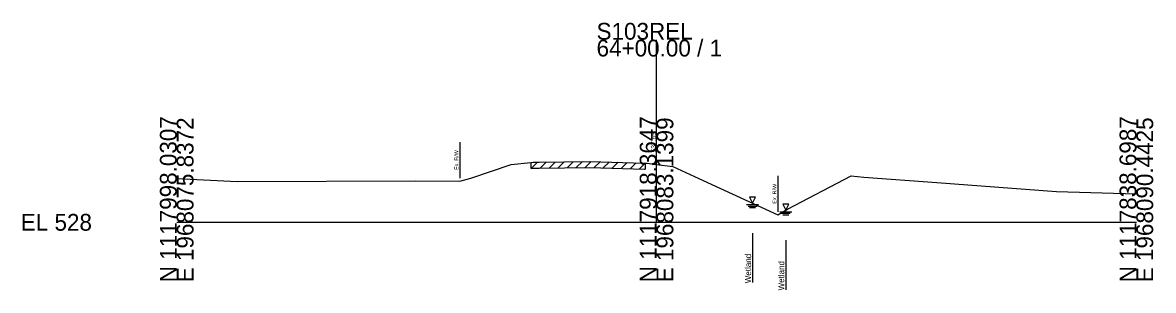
# Model space of a CAD drawing. Extents: x -26 to 163, y -10 to 24518.
# Drawn here: x -25.7 to 162.8, y 11988.6 to 12033.3 of the extents above; entities that cross this region are included whole.
import ezdxf

# ---------------------------------------------------------------- set-up
doc = ezdxf.new("R2010")
doc.units = 0
for name, color, linetype in [('RD_GPK_XS_Cell', 7, 'Continuous'), ('RD_XS_ExGround', 7, 'Continuous'), ('RD_XS_ExPaveRet', 7, 'Continuous'), ('RD_XS_ExRW', 7, 'Continuous'), ('RD_XS_EXWetland', 7, 'Continuous'), ('RD_XS_TX_Elev_EX', 7, 'Continuous')]:
    doc.layers.add(name, color=color, linetype=linetype)

msp = doc.modelspace()

# ---------------------------------------------------------------- linework, layer by layer
at = {"layer": 'RD_GPK_XS_Cell'}
for p, q in [((80, 12000), (80, 12030.44)), ((0, 12000), (80, 12000)), ((80, 12000), (160, 12000))]:
    msp.add_line(p, q, dxfattribs=at)
at = {"layer": 'RD_XS_ExGround'}
msp.add_lwpolyline([(0, 12007.32), (10.08, 12006.8), (39.8, 12006.92), (47.23, 12006.88), (49.04, 12007.38), (55.74, 12009.63), (59.04, 12009.96), (59.43, 12010), (60.41, 12010), (68.87, 12010.15), (77.99, 12009.86), (78.45, 12009.84), (80, 12009.65), (82.73, 12009.31), (87.78, 12006.98), (100.24, 12001.26), (101.85, 12002.18), (112.46, 12007.76), (114.57, 12007.52), (126.73, 12006.66), (146.71, 12005.13), (160, 12004.73)], dxfattribs=at)
at = {"layer": 'RD_XS_ExPaveRet'}
for p, q in [((59.09, 12008.96), (60.13, 12010)), ((59.09, 12008.96), (59.09, 12009.96)), ((60.59, 12009.01), (61.61, 12010.03)), ((62.1, 12009.03), (63.12, 12010.05)), ((63.6, 12009.06), (64.62, 12010.08)), ((65.1, 12009.08), (66.12, 12010.1)), ((66.61, 12009.11), (67.63, 12010.13)), ((68.11, 12009.14), (69.12, 12010.14)), ((69.61, 12009.12), (70.59, 12010.09)), ((71.12, 12009.08), (72.09, 12010.05)), ((72.62, 12009.03), (73.59, 12010)), ((74.12, 12008.98), (75.1, 12009.95)), ((75.63, 12008.93), (76.6, 12009.9)), ((77.13, 12008.88), (78.1, 12009.85)), ((78.13, 12009.85), (78.13, 12008.85)), ((59.09, 12008.96), (59.43, 12009)), ((59.43, 12009), (60.41, 12009)), ((60.41, 12009), (68.87, 12009.15)), ((68.87, 12009.15), (77.99, 12008.86)), ((77.99, 12008.86), (78.13, 12008.85))]:
    msp.add_line(p, q, dxfattribs=at)
at = {"layer": 'RD_XS_ExRW'}
for p, q in [((47.21, 12013.38), (47.21, 12007.38)), ((100.25, 12007.76), (100.25, 12001.76))]:
    msp.add_line(p, q, dxfattribs=at)
at = {"layer": 'RD_XS_EXWetland'}
for p, q in [((95.52, 12004.2), (96.02, 12003.2)), ((96.52, 12004.2), (95.52, 12004.2)), ((95.52, 12004.2), (96.02, 12003.2)), ((96.52, 12004.2), (95.52, 12004.2)), ((96.02, 12003.2), (96.52, 12004.2)), ((96.02, 12003.2), (96.52, 12004.2)), ((95.02, 12002.95), (97.02, 12002.95)), ((95.02, 12002.95), (97.02, 12002.95)), ((95.27, 12002.7), (96.77, 12002.7)), ((95.27, 12002.7), (96.77, 12002.7)), ((95.52, 12002.45), (96.52, 12002.45)), ((95.52, 12002.45), (96.52, 12002.45)), ((101.04, 12003), (101.54, 12002)), ((102.04, 12003), (101.04, 12003)), ((101.04, 12003), (101.54, 12002)), ((102.04, 12003), (101.04, 12003)), ((101.54, 12002), (102.04, 12003)), ((101.54, 12002), (102.04, 12003)), ((100.54, 12001.75), (102.54, 12001.75)), ((100.54, 12001.75), (102.54, 12001.75)), ((100.79, 12001.5), (102.29, 12001.5)), ((100.79, 12001.5), (102.29, 12001.5)), ((101.04, 12001.25), (102.04, 12001.25)), ((101.04, 12001.25), (102.04, 12001.25)), ((96.02, 11998.2), (96.02, 11989.95)), ((96.02, 11998.2), (96.02, 11989.95)), ((101.54, 11997), (101.54, 11988.75)), ((101.54, 11997), (101.54, 11988.75))]:
    msp.add_line(p, q, dxfattribs=at)

# ---------------------------------------------------------------- texts
at = {"layer": 'RD_GPK_XS_Cell'}
for s, p in [('S103REL', (70, 12030.44)), ('64+00.00 / 1', (70, 12027.64)), ('EL 528', (-26, 11998.6))]:
    msp.add_text(s, height=2.8, dxfattribs=at).set_placement(p)
for s, p in [('N 1117998.0307', (0, 11990)), ('E 1968075.8372', (2.8, 11990)), ('N 1117918.3647', (80, 11990)), ('E 1968083.1399', (82.8, 11990)), ('N 1117838.6987', (160, 11990)), ('E 1968090.4425', (162.8, 11990))]:
    msp.add_text(s, height=2.8, rotation=90, dxfattribs=at).set_placement(p)
at = {"layer": 'RD_XS_ExRW'}
for p in [(46.96, 12008.73), (100, 12003.11)]:
    msp.add_text('Ex. R/W ', height=0.65, rotation=90, dxfattribs=at).set_placement(p)
at = {"layer": 'RD_XS_EXWetland'}
for p in [(95.77, 11989.84), (95.77, 11989.84), (101.29, 11988.64), (101.29, 11988.64)]:
    msp.add_text('Wetland ', height=1, rotation=90, dxfattribs=at).set_placement(p)
at = {"layer": 'RD_XS_TX_Elev_EX'}
msp.add_text('537.65', height=0.8, rotation=90, dxfattribs=at).set_placement((79.9, 12011.65))

doc.saveas('drawing.dxf')
